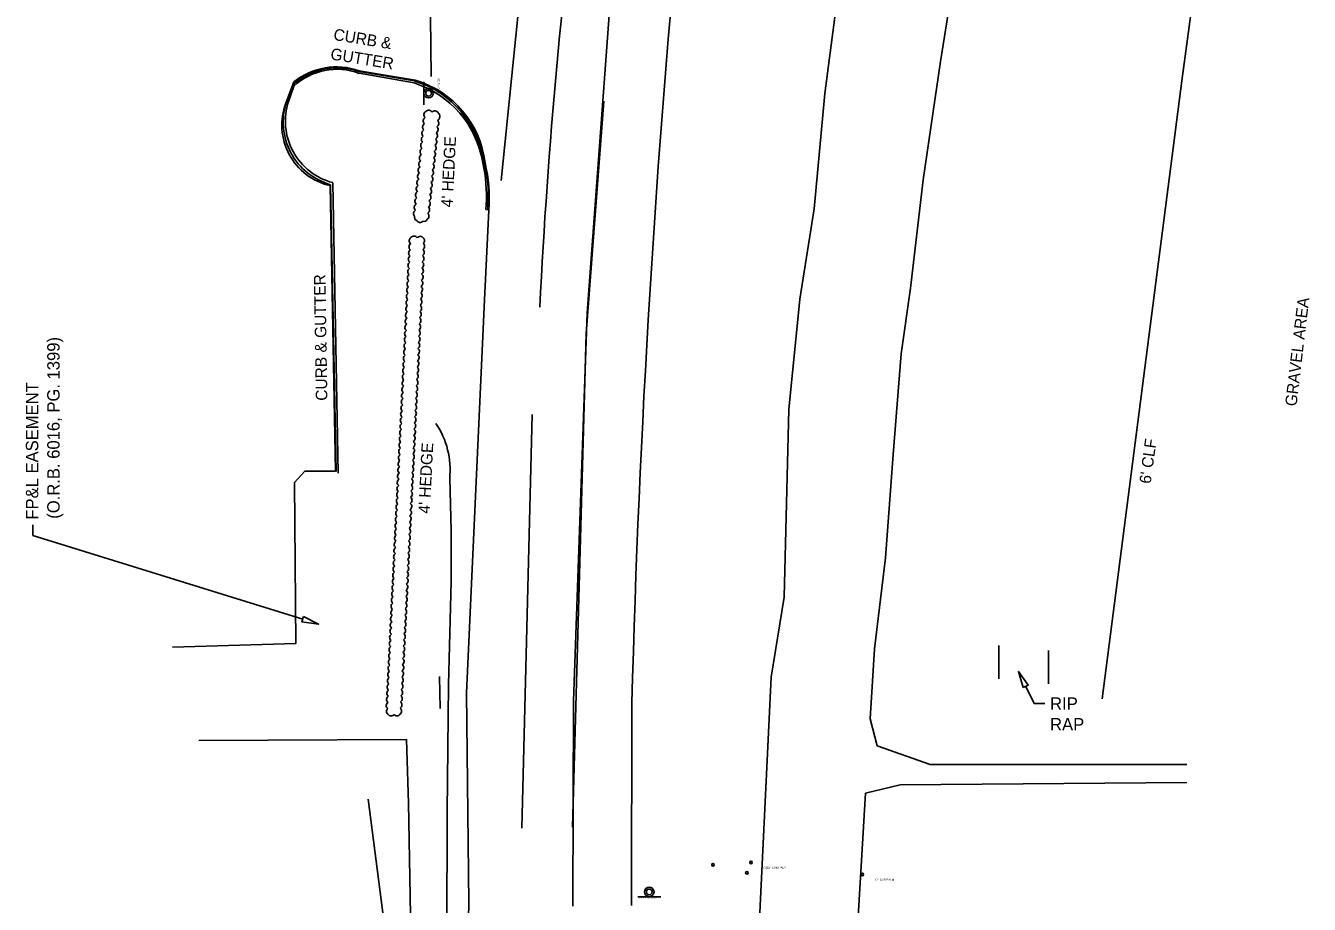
# Model space of a CAD drawing. Extents: x 925226 to 926411, y 852913 to 858733.
# Drawn here: x 925645 to 925955.3, y 857328.5 to 857540.8 of the extents above; entities that cross this region are included whole.
import ezdxf

# ---------------------------------------------------------------- set-up
doc = ezdxf.new("R2010")
doc.units = 0
for name, color, linetype in [('CGFace_ep', 7, 'Continuous'), ('CLConst_dp', 7, 'Continuous'), ('CurveData_dp', 7, 'Continuous'), ('EndTreat_ep', 7, 'Continuous'), ('Fence_ep', 7, 'Continuous'), ('InletDBI_ep', 7, 'Continuous'), ('ManholeSW_ep', 7, 'Continuous'), ('PavtAsphalt_ep', 7, 'Continuous'), ('PavtCrown_ep', 7, 'Continuous'), ('PavtMisc_ep', 7, 'Continuous'), ('RipRap_ep', 7, 'Continuous'), ('TextLabel', 7, 'Continuous'), ('WaterEdge_ep', 7, 'Continuous'), ('XSPt_ep', 7, 'Continuous')]:
    doc.layers.add(name, color=color, linetype=linetype)

# ---------------------------------------------------------------- blocks, each defined once
blk = doc.blocks.new('SSS')
at = {"layer": 'ManholeSW_ep'}
blk.add_line((-2.77, 1.15), (2.77, 1.15), dxfattribs=at)
for radius in [1.15, 0.692]:
    blk.add_circle((0, 0), radius, dxfattribs=at)
blk = doc.blocks.new('TREEPA')
at = {"layer": 'InletDBI_ep'}
blk.add_circle((0, 0), 0.3, dxfattribs=at)

msp = doc.modelspace()

# ---------------------------------------------------------------- linework, layer by layer
at = {"layer": 'CGFace_ep'}
for p, q in [((925739.06, 857527.46), (925725.56, 857529.72)), ((925708.06, 857522.37), (925710.02, 857526.9)), ((925720.05, 857433.05), (925718.75, 857502.39)), ((925756.71, 857497.57), (925756.77, 857496.42))]:
    msp.add_line(p, q, dxfattribs=at)
for centre, major_axis, ratio, start_param, end_param in [((925720.29, 857514.72), (15.37, -4.12), 0.999223, 1.494784, 2.530766), ((925731.85, 857504.38), (18.32, 15.78), 0.999389, 5.70898, 6.840019), ((925722.96, 857517.47), (-13.47, 8.03), 0.997976, 0.219797, 1.835648), ((925729.9, 857500.26), (24.69, 10.78), 0.999619, 5.771737, 6.151155)]:
    msp.add_ellipse(centre, major_axis=major_axis, ratio=ratio, start_param=start_param, end_param=end_param, dxfattribs=at)
at = {"layer": 'CurveData_dp'}
for p, q in [((925747.91, 857418.71), (925747.54, 857431.43)), ((925747.86, 857406.59), (925747.91, 857418.71)), ((925747.27, 857381.51), (925747.86, 857406.59)), ((925746.92, 857350.84), (925747.27, 857381.51)), ((925746.72, 857294.62), (925746.92, 857350.84))]:
    msp.add_line(p, q, dxfattribs=at)
msp.add_ellipse((925727.7, 857433.42), major_axis=(1.23, 20.01), ratio=0.994232, start_param=4.673603, end_param=5.368645, dxfattribs=at)
at = {"layer": 'EndTreat_ep'}
for p, q in [((925759.99, 857503.37), (925765.86, 857561.58)), ((925742.91, 857542.98), (925743.08, 857528.57)), ((925780.53, 857466.41), (925784.77, 857522.56)), ((925777.17, 857347.1), (925780.53, 857466.41)), ((925764.98, 857346.9), (925767.44, 857446.83))]:
    msp.add_line(p, q, dxfattribs=at)
msp.add_ellipse((927147.67, 857404.96), major_axis=(-627.46, -1229.21), ratio=0.99994, start_param=5.050538, end_param=5.135171, dxfattribs=at)
at = {"layer": 'Fence_ep'}
for p, q in [((925946.09, 857691.45), (925924.52, 857527.46)), ((925924.52, 857527.46), (925905.25, 857378.11)), ((925686.93, 857368.08), (925737.12, 857368.32)), ((925737.12, 857368.32), (925737.58, 857352.89)), ((925737.58, 857352.89), (925738.56, 857294.74))]:
    msp.add_line(p, q, dxfattribs=at)
at = {"layer": 'InletDBI_ep'}
for centre, radius, start, end in [((925742.06, 857517.81), 0.916, 119.0057, 229.0057), ((925742.21, 857519.3), 0.916, 119.0057, 229.0057), ((925742.46, 857519.5), 0.916, 29.0057, 139.0057), ((925743.95, 857519.34), 0.916, 29.0057, 139.0057), ((925743.99, 857518.91), 1.16, 299.0057, 49.0057), ((925741.74, 857514.83), 0.916, 119.0057, 229.0057), ((925741.9, 857516.32), 0.916, 119.0057, 229.0057), ((925743.8, 857515.72), 0.916, 299.0057, 49.0057), ((925743.96, 857517.21), 0.916, 299.0057, 49.0057), ((925741.43, 857511.84), 0.916, 119.0057, 229.0057), ((925741.59, 857513.33), 0.916, 119.0057, 229.0057), ((925743.49, 857512.74), 0.916, 299.0057, 49.0057), ((925743.64, 857514.23), 0.916, 299.0057, 49.0057), ((925741.12, 857508.86), 0.916, 119.0057, 229.0057), ((925741.27, 857510.35), 0.916, 119.0057, 229.0057), ((925743.17, 857509.75), 0.916, 299.0057, 49.0057), ((925743.33, 857511.24), 0.916, 299.0057, 49.0057), ((925740.8, 857505.87), 0.916, 119.0057, 229.0057), ((925740.96, 857507.37), 0.916, 119.0057, 229.0057), ((925742.86, 857506.77), 0.916, 299.0057, 49.0057), ((925743.02, 857508.26), 0.916, 299.0057, 49.0057), ((925740.49, 857502.89), 0.916, 119.0057, 229.0057), ((925740.65, 857504.38), 0.916, 119.0057, 229.0057), ((925742.55, 857503.78), 0.916, 299.0057, 49.0057), ((925742.7, 857505.28), 0.916, 299.0057, 49.0057), ((925740.18, 857499.91), 0.916, 119.0057, 229.0057), ((925740.33, 857501.4), 0.916, 119.0057, 229.0057), ((925742.08, 857499.31), 0.916, 299.0057, 49.0057), ((925742.23, 857500.8), 0.916, 299.0057, 49.0057), ((925742.39, 857502.29), 0.916, 299.0057, 49.0057), ((925739.86, 857496.92), 0.916, 119.0057, 229.0057), ((925740.02, 857498.42), 0.916, 119.0057, 229.0057), ((925741.76, 857496.33), 0.916, 299.0057, 49.0057), ((925741.92, 857497.82), 0.916, 299.0057, 49.0057), ((925739.71, 857495.43), 0.916, 119.0057, 229.0057), ((925739.68, 857494.4), 0.67, 149.1734, 259.1734), ((925740.36, 857494.18), 0.916, 209.0057, 319.0057), ((925741.39, 857494.16), 0.67, 239.1734, 349.1734), ((925741.61, 857494.83), 0.916, 299.0057, 49.0057), ((925738.59, 857487.36), 0.916, 122.1718, 232.1718), ((925738.66, 857488.86), 0.916, 122.1718, 232.1718), ((925738.9, 857489.07), 0.916, 32.1718, 142.1718), ((925740.39, 857489), 0.916, 32.1718, 142.1718), ((925740.55, 857487.54), 0.916, 302.1718, 52.1718), ((925740.71, 857488.9), 0.747, 302.1718, 52.1718), ((925738.44, 857484.37), 0.916, 122.1718, 232.1718), ((925738.51, 857485.86), 0.916, 122.1718, 232.1718), ((925740.4, 857484.55), 0.916, 302.1718, 52.1718), ((925740.47, 857486.05), 0.916, 302.1718, 52.1718), ((925738.29, 857481.37), 0.916, 122.1718, 232.1718), ((925738.36, 857482.87), 0.916, 122.1718, 232.1718), ((925740.25, 857481.55), 0.916, 302.1718, 52.1718), ((925740.33, 857483.05), 0.916, 302.1718, 52.1718), ((925738.14, 857478.37), 0.916, 122.1718, 232.1718), ((925738.22, 857479.87), 0.916, 122.1718, 232.1718), ((925740.1, 857478.55), 0.916, 302.1718, 52.1718), ((925740.18, 857480.05), 0.916, 302.1718, 52.1718), ((925737.99, 857475.38), 0.916, 122.1718, 232.1718), ((925738.07, 857476.88), 0.916, 122.1718, 232.1718), ((925739.96, 857475.56), 0.916, 302.1718, 52.1718), ((925740.03, 857477.06), 0.916, 302.1718, 52.1718), ((925737.85, 857472.38), 0.916, 122.1718, 232.1718), ((925737.92, 857473.88), 0.916, 122.1718, 232.1718), ((925739.81, 857472.56), 0.916, 302.1718, 52.1718), ((925739.88, 857474.06), 0.916, 302.1718, 52.1718), ((925737.7, 857469.38), 0.916, 122.1718, 232.1718), ((925737.77, 857470.88), 0.916, 122.1718, 232.1718), ((925739.66, 857469.57), 0.916, 302.1718, 52.1718), ((925739.73, 857471.06), 0.916, 302.1718, 52.1718), ((925737.55, 857466.39), 0.916, 122.1718, 232.1718), ((925737.62, 857467.89), 0.916, 122.1718, 232.1718), ((925739.44, 857465.07), 0.916, 302.1718, 52.1718), ((925739.51, 857466.57), 0.916, 302.1718, 52.1718), ((925739.59, 857468.07), 0.916, 302.1718, 52.1718), ((925737.33, 857461.89), 0.916, 122.1718, 232.1718), ((925737.4, 857463.39), 0.916, 122.1718, 232.1718), ((925737.48, 857464.89), 0.916, 122.1718, 232.1718), ((925739.29, 857462.07), 0.916, 302.1718, 52.1718), ((925739.36, 857463.57), 0.916, 302.1718, 52.1718), ((925737.18, 857458.9), 0.916, 122.1718, 232.1718), ((925737.25, 857460.4), 0.916, 122.1718, 232.1718), ((925739.14, 857459.08), 0.916, 302.1718, 52.1718), ((925739.22, 857460.58), 0.916, 302.1718, 52.1718), ((925737.03, 857455.9), 0.916, 122.1718, 232.1718), ((925737.11, 857457.4), 0.916, 122.1718, 232.1718), ((925738.99, 857456.08), 0.916, 302.1718, 52.1718), ((925739.07, 857457.58), 0.916, 302.1718, 52.1718), ((925736.88, 857452.9), 0.916, 122.1718, 232.1718), ((925736.96, 857454.4), 0.916, 122.1718, 232.1718), ((925738.85, 857453.09), 0.916, 302.1718, 52.1718), ((925738.92, 857454.58), 0.916, 302.1718, 52.1718), ((925736.74, 857449.91), 0.916, 122.1718, 232.1718), ((925736.81, 857451.41), 0.916, 122.1718, 232.1718), ((925738.7, 857450.09), 0.916, 302.1718, 52.1718), ((925738.77, 857451.59), 0.916, 302.1718, 52.1718), ((925736.59, 857446.91), 0.916, 122.1718, 232.1718), ((925736.66, 857448.41), 0.916, 122.1718, 232.1718), ((925738.55, 857447.09), 0.916, 302.1718, 52.1718), ((925738.62, 857448.59), 0.916, 302.1718, 52.1718), ((925736.44, 857443.92), 0.916, 122.1718, 232.1718), ((925736.51, 857445.41), 0.916, 122.1718, 232.1718), ((925738.4, 857444.1), 0.916, 302.1718, 52.1718), ((925738.48, 857445.59), 0.916, 302.1718, 52.1718), ((925736.29, 857440.92), 0.916, 122.1718, 232.1718), ((925736.37, 857442.42), 0.916, 122.1718, 232.1718), ((925738.25, 857441.1), 0.916, 302.1718, 52.1718), ((925738.33, 857442.6), 0.916, 302.1718, 52.1718), ((925736.14, 857437.92), 0.916, 122.1718, 232.1718), ((925736.22, 857439.42), 0.916, 122.1718, 232.1718), ((925738.1, 857438.1), 0.916, 302.1718, 52.1718), ((925738.18, 857439.6), 0.916, 302.1718, 52.1718), ((925736, 857434.93), 0.916, 122.1718, 232.1718), ((925736.07, 857436.42), 0.916, 122.1718, 232.1718), ((925737.96, 857435.11), 0.916, 302.1718, 52.1718), ((925738.03, 857436.61), 0.916, 302.1718, 52.1718), ((925735.85, 857431.93), 0.916, 122.1718, 232.1718), ((925735.92, 857433.43), 0.916, 122.1718, 232.1718), ((925737.81, 857432.11), 0.916, 302.1718, 52.1718), ((925737.88, 857433.61), 0.916, 302.1718, 52.1718), ((925735.7, 857428.93), 0.916, 122.1718, 232.1718), ((925735.77, 857430.43), 0.916, 122.1718, 232.1718), ((925737.66, 857429.11), 0.916, 302.1718, 52.1718), ((925737.73, 857430.61), 0.916, 302.1718, 52.1718), ((925735.55, 857425.94), 0.916, 122.1718, 232.1718), ((925735.63, 857427.44), 0.916, 122.1718, 232.1718), ((925737.51, 857426.12), 0.916, 302.1718, 52.1718), ((925737.59, 857427.62), 0.916, 302.1718, 52.1718), ((925735.4, 857422.94), 0.916, 122.1718, 232.1718), ((925735.48, 857424.44), 0.916, 122.1718, 232.1718), ((925737.29, 857421.62), 0.916, 302.1718, 52.1718), ((925737.36, 857423.12), 0.916, 302.1718, 52.1718), ((925737.44, 857424.62), 0.916, 302.1718, 52.1718), ((925735.18, 857418.45), 0.916, 122.1718, 232.1718), ((925735.26, 857419.95), 0.916, 122.1718, 232.1718), ((925735.33, 857421.44), 0.916, 122.1718, 232.1718), ((925737.14, 857418.63), 0.916, 302.1718, 52.1718), ((925737.22, 857420.13), 0.916, 302.1718, 52.1718), ((925735.03, 857415.45), 0.916, 122.1718, 232.1718), ((925735.11, 857416.95), 0.916, 122.1718, 232.1718), ((925736.99, 857415.63), 0.916, 302.1718, 52.1718), ((925737.07, 857417.13), 0.916, 302.1718, 52.1718), ((925734.89, 857412.45), 0.916, 122.1718, 232.1718), ((925734.96, 857413.95), 0.916, 122.1718, 232.1718), ((925736.85, 857412.63), 0.916, 302.1718, 52.1718), ((925736.92, 857414.13), 0.916, 302.1718, 52.1718), ((925734.74, 857409.46), 0.916, 122.1718, 232.1718), ((925734.81, 857410.96), 0.916, 122.1718, 232.1718), ((925736.7, 857409.64), 0.916, 302.1718, 52.1718), ((925736.77, 857411.14), 0.916, 302.1718, 52.1718), ((925734.59, 857406.46), 0.916, 122.1718, 232.1718), ((925734.66, 857407.96), 0.916, 122.1718, 232.1718), ((925736.55, 857406.64), 0.916, 302.1718, 52.1718), ((925736.62, 857408.14), 0.916, 302.1718, 52.1718), ((925734.44, 857403.47), 0.916, 122.1718, 232.1718), ((925734.52, 857404.96), 0.916, 122.1718, 232.1718), ((925736.4, 857403.65), 0.916, 302.1718, 52.1718), ((925736.48, 857405.14), 0.916, 302.1718, 52.1718), ((925734.29, 857400.47), 0.916, 122.1718, 232.1718), ((925734.37, 857401.97), 0.916, 122.1718, 232.1718), ((925736.25, 857400.65), 0.916, 302.1718, 52.1718), ((925736.33, 857402.15), 0.916, 302.1718, 52.1718), ((925734.15, 857397.47), 0.916, 122.1718, 232.1718), ((925734.22, 857398.97), 0.916, 122.1718, 232.1718), ((925736.11, 857397.65), 0.916, 302.1718, 52.1718), ((925736.18, 857399.15), 0.916, 302.1718, 52.1718), ((925734, 857394.48), 0.916, 122.1718, 232.1718), ((925734.07, 857395.97), 0.916, 122.1718, 232.1718), ((925735.96, 857394.66), 0.916, 302.1718, 52.1718), ((925736.03, 857396.15), 0.916, 302.1718, 52.1718), ((925733.85, 857391.48), 0.916, 122.1718, 232.1718), ((925733.92, 857392.98), 0.916, 122.1718, 232.1718), ((925735.81, 857391.66), 0.916, 302.1718, 52.1718), ((925735.88, 857393.16), 0.916, 302.1718, 52.1718), ((925733.7, 857388.48), 0.916, 122.1718, 232.1718), ((925733.78, 857389.98), 0.916, 122.1718, 232.1718), ((925735.66, 857388.66), 0.916, 302.1718, 52.1718), ((925735.74, 857390.16), 0.916, 302.1718, 52.1718), ((925733.55, 857385.49), 0.916, 122.1718, 232.1718), ((925733.63, 857386.99), 0.916, 122.1718, 232.1718), ((925735.51, 857385.67), 0.916, 302.1718, 52.1718), ((925735.59, 857387.17), 0.916, 302.1718, 52.1718), ((925733.41, 857382.49), 0.916, 122.1718, 232.1718), ((925733.48, 857383.99), 0.916, 122.1718, 232.1718), ((925735.37, 857382.67), 0.916, 302.1718, 52.1718), ((925735.44, 857384.17), 0.916, 302.1718, 52.1718), ((925733.26, 857379.49), 0.916, 122.1718, 232.1718), ((925733.33, 857380.99), 0.916, 122.1718, 232.1718), ((925735.14, 857378.18), 0.916, 302.1718, 52.1718), ((925735.22, 857379.67), 0.916, 302.1718, 52.1718), ((925735.29, 857381.17), 0.916, 302.1718, 52.1718), ((925733.11, 857376.5), 0.916, 122.1718, 232.1718), ((925733.18, 857378), 0.916, 122.1718, 232.1718), ((925735, 857375.18), 0.916, 302.1718, 52.1718), ((925735.07, 857376.68), 0.916, 302.1718, 52.1718), ((925733.06, 857375.12), 0.835, 127.9799, 237.9799), ((925733.39, 857374.9), 0.916, 212.1718, 322.1718), ((925734.78, 857374.85), 0.835, 217.9799, 327.9799)]:
    msp.add_arc(centre, radius, start, end, dxfattribs=at)
at = {"layer": 'PavtAsphalt_ep'}
for p, q in [((925755.91, 857474.54), (925757.01, 857496.26)), ((925751.61, 857379.55), (925755.91, 857474.54)), ((925745.25, 857375.77), (925745.09, 857383.55)), ((925752.18, 857328.77), (925751.61, 857379.55)), ((925791.44, 857328.16), (925791.58, 857377.12)), ((925751.42, 857295.53), (925752.18, 857328.77))]:
    msp.add_line(p, q, dxfattribs=at)
for centre, major_axis, ratio, start_param, end_param in [((928603.71, 857303.24), (33.77, -2818.01), 0.998185, 4.604015, 4.674208), ((925732.46, 857504.84), (-22.11, -8.8), 0.999393, 2.883409, 4.046087), ((925717.77, 857498.82), (-17.32, -35.34), 0.998911, 1.961048, 2.253944)]:
    msp.add_ellipse(centre, major_axis=major_axis, ratio=ratio, start_param=start_param, end_param=end_param, dxfattribs=at)
at = {"layer": 'PavtCrown_ep'}
for p, q in [((925780.72, 857471.45), (925788.69, 857577.98)), ((925777.48, 857377.55), (925780.72, 857471.45)), ((925777.27, 857328.03), (925777.48, 857377.55))]:
    msp.add_line(p, q, dxfattribs=at)
at = {"layer": 'PavtMisc_ep'}
for p, q in [((925725.63, 857529.94), (925739.22, 857527.65)), ((925707.92, 857522.11), (925709.88, 857527.23)), ((925718.61, 857502.18), (925719.89, 857433.17)), ((925712.49, 857433.15), (925710, 857430.38)), ((925719.89, 857433.17), (925712.49, 857433.15)), ((925710, 857430.38), (925710.34, 857391.54)), ((925680.52, 857390.61), (925710.34, 857391.54)), ((925735.05, 857297.96), (925727.82, 857353.91))]:
    msp.add_line(p, q, dxfattribs=at)
for centre, major_axis, ratio, start_param, end_param in [((925720.21, 857514.42), (-15.98, 3.97), 0.998907, 4.619987, 5.633873), ((925721.97, 857516.8), (-14.98, 1.02), 0.999063, 5.989587, 7.69645)]:
    msp.add_ellipse(centre, major_axis=major_axis, ratio=ratio, start_param=start_param, end_param=end_param, dxfattribs=at)
at = {"layer": 'RipRap_ep'}
for p, q in [((925880.24, 857390.99), (925880.26, 857382.95)), ((925892.23, 857389.82), (925892.25, 857381.78))]:
    msp.add_line(p, q, dxfattribs=at)
at = {"layer": 'TextLabel'}
for points in [[(925646.74, 857417.61), (925646.74, 857420.15)], [(925712, 857397.36), (925646.74, 857417.61)], [(925886.76, 857381.15), (925888.83, 857376.98)], [(925888.83, 857376.98), (925891.36, 857376.98)]]:
    msp.add_lwpolyline(points, dxfattribs=at)
for points in [[(925712.2, 857398), (925715.82, 857396.18), (925711.81, 857396.72)], [(925886.16, 857380.86), (925884.98, 857384.74), (925887.36, 857381.45)]]:
    msp.add_lwpolyline(points, close=True, dxfattribs=at)
at = {"layer": 'WaterEdge_ep'}
for p, q in [((925866.14, 857532.16), (925871.02, 857562.22)), ((925842.08, 857553.96), (925838.2, 857524.41)), ((925861.97, 857503.53), (925866.14, 857532.16)), ((925838.2, 857524.41), (925835.65, 857496.53)), ((925858.87, 857477.35), (925861.97, 857503.53)), ((925835.65, 857496.53), (925832.12, 857474.72)), ((925856.69, 857461.48), (925858.87, 857477.35)), ((925832.12, 857474.72), (925829.5, 857448.1)), ((925854.72, 857437.19), (925856.69, 857461.48)), ((925829.5, 857448.1), (925828.37, 857402.69)), ((925852.87, 857412.25), (925854.72, 857437.19)), ((925850.18, 857390.2), (925852.87, 857412.25)), ((925828.37, 857402.69), (925825.22, 857383.36)), ((925850.18, 857390.2), (925849.15, 857373.33)), ((925825.22, 857383.36), (925818.02, 857232.12)), ((925849.15, 857373.33), (925850.88, 857366.74)), ((925850.88, 857366.74), (925863.67, 857362.27)), ((925863.67, 857362.27), (925925.72, 857362.27)), ((925856.42, 857357.37), (925848.06, 857355.32)), ((925925.72, 857357.91), (925856.42, 857357.37)), ((925848.06, 857355.32), (925842.49, 857263.79))]:
    msp.add_line(p, q, dxfattribs=at)
at = {"layer": 'XSPt_ep'}
for p, q in [((925738.95, 857526.99), (925725.65, 857529.31)), ((925709.88, 857526.2), (925708.56, 857522.53)), ((925719.25, 857502.88), (925720.53, 857432.65)), ((925756.28, 857496.43), (925756.35, 857497.56)), ((925756.28, 857496.43), (925756.77, 857496.42))]:
    msp.add_line(p, q, dxfattribs=at)
msp.add_arc((925723.21, 857517.77), 15.4, 161.9967, 255.1208, dxfattribs=at)
for centre, major_axis, ratio, start_param, end_param in [((925720.27, 857515.09), (14.59, -4.29), 0.999214, 1.495209, 2.608723), ((925731.65, 857503.97), (-12.78, -20.48), 0.999303, 2.281287, 3.39284), ((925721.67, 857499.73), (-27.13, -21.71), 0.999496, 2.403807, 2.696306)]:
    msp.add_ellipse(centre, major_axis=major_axis, ratio=ratio, start_param=start_param, end_param=end_param, dxfattribs=at)

# ---------------------------------------------------------------- block references
at = {"layer": 'InletDBI_ep'}
for p in [(925820.36, 857338.58), (925811.15, 857338.01), (925819.36, 857336.07), (925847.27, 857335.68)]:
    msp.add_blockref('TREEPA', p, dxfattribs=at)
at = {"layer": 'ManholeSW_ep'}
for p, rotation in [((925742.43, 857524.5), 89.99999999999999), ((925795.76, 857331.46), 180)]:
    msp.add_blockref('SSS', p, dxfattribs=dict(at, rotation=rotation))

# ---------------------------------------------------------------- texts
at = {"layer": 'CLConst_dp'}
for s, rotation, p in [('STOP SIGN', 90, (925745.1, 857524.5)), ('TRAFFIC LIGHT', 0.4185, (925792.99, 857329.92))]:
    msp.add_text(s, height=0.5, rotation=rotation, dxfattribs=at).set_placement(p)
for s, p in [('(3)15" CAB PALM', (925823.36, 857337.1)), ('15" CAB PALM', (925850.27, 857334.16))]:
    msp.add_text(s, height=0.5, dxfattribs=at).set_placement(p)
at = {"layer": 'TextLabel'}
for s, height, rotation, p in [('CURB & ', 2.8, 350.7882, (925719.29, 857537.4)), ('GUTTER', 2.8, 350.7882, (925718.56, 857532.7)), ("4' HEDGE", 2.8, 87.1718, (925748.23, 857496.87)), ('CURB & GUTTER', 2.8, 90.8912, (925717.97, 857450.2)), ('GRAVEL AREA', 2.8, 83.237, (925952.2, 857448.73)), ('(O.R.B. 6016, PG. 1399)', 3, 90, (925653.25, 857421.66)), ('FP&L EASEMENT', 3, 90, (925648.08, 857421.44)), ("6' CLF", 2.8, 82.3363, (925916.96, 857430)), ("4' HEDGE", 2.8, 87.1718, (925742.72, 857422.84)), ('RIP', 3, 360, (925892.65, 857375.48)), ('RAP', 3, 360, (925892.65, 857370.48))]:
    msp.add_text(s, height=height, rotation=rotation, dxfattribs=at).set_placement(p)

doc.saveas('drawing.dxf')
